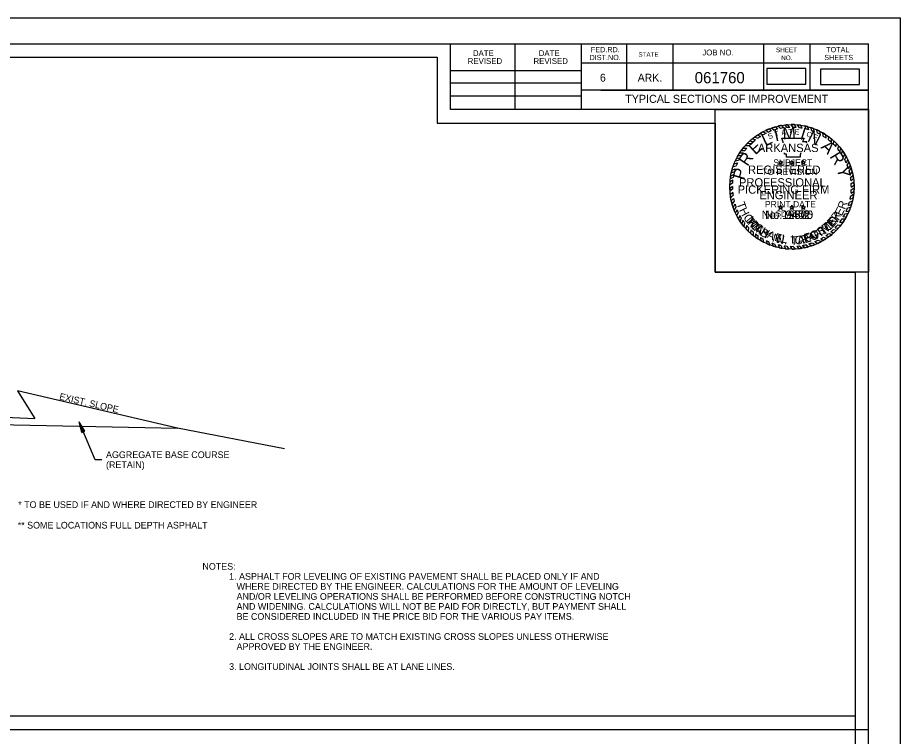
# Model space of a CAD drawing. Extents: x -124 to 3209, y -40 to 2094.
# Drawn here: x 1887 to 3209, y 1017 to 2094 of the extents above; entities that cross this region are included whole.
import ezdxf

# ---------------------------------------------------------------- set-up
doc = ezdxf.new("R2010")
doc.units = 0
for name, color, linetype in [('Default', 7, 'Continuous'), ('R_Border', 7, 'Continuous'), ('R_Border Notes', 7, 'Continuous'), ('R_Border Plan-Plan', 7, 'Continuous'), ('R_No Plot', 7, 'Continuous'), ('STAMP_PE_CRAFTON', 7, 'Continuous'), ('STAMP_PE_FOSTER', 7, 'Continuous'), ('STAMP_PE_SEAL-INFO', 7, 'Continuous'), ('STAMP_PE_TAEGTMEYER', 7, 'Continuous'), ('STAMP_PE_TXT', 7, 'Continuous'), ('STAMP_PRELIMINARY', 7, 'Continuous'), ('Text', 7, 'Continuous')]:
    doc.layers.add(name, color=color, linetype=linetype)

msp = doc.modelspace()

# ---------------------------------------------------------------- linework, layer by layer
at = {"layer": 'Default'}
for p, q in [((1886.3, 1534.5), (1912.2, 1493.4)), ((2126.3, 1478.9), (1886.3, 1534.5)), ((1685.5, 1502.5), (1912.2, 1493.4)), ((1706.3, 1487.1), (2126.3, 1478.9)), ((2286.3, 1447.9), (2126.3, 1478.9))]:
    msp.add_line(p, q, dxfattribs=at)
for points in [[(3009.4, 1994.1), (3067.8, 1994.1), (3067.8, 2017.2), (3009.4, 2017.2)], [(3089.7, 1993.3), (3148, 1993.3), (3148, 2016.4), (3089.7, 2016.4)]]:
    msp.add_lwpolyline(points, close=True, dxfattribs=at)
at = {"layer": 'R_Border'}
for p, q in [((0, 2054.6), (3161.8, 2054.6)), ((2535.4, 1955.8), (2535.4, 2054.6)), ((2632.2, 1955.8), (2632.2, 2054.6)), ((2730.8, 2054.6), (2730.8, 1955.8)), ((2799.2, 2054.6), (2799.2, 1985.2)), ((2868.6, 2054.6), (2868.6, 1985.2)), ((3004.4, 2054.6), (3004.4, 1985.2)), ((3073.8, 2054.6), (3073.8, 1985.2)), ((3161.8, 0), (3161.8, 2054.6)), ((3161.8, 2025.2), (2730.8, 2025.2)), ((3161.8, 2025.4), (3161.8, 2025.4)), ((2535.4, 2014.4), (2730.8, 2014.4)), ((2535.4, 1995.8), (2730.8, 1995.8)), ((3161.8, 1985.2), (2730.8, 1985.2)), ((2760.4, 1985.2), (3161.8, 1985.2)), ((2535.4, 1976.4), (2730.8, 1976.4)), ((3161.8, 1955.8), (2535.4, 1955.8))]:
    msp.add_line(p, q, dxfattribs=at)
at = {"layer": 'R_Border Plan-Plan'}
msp.add_line((0, 1027.3), (3161.8, 1027.3), dxfattribs=at)
at = {"layer": 'R_No Plot'}
for points in [[(-124.1, 2093.5), (3209.3, 2093.5), (3209.3, -39.8), (-124.1, -39.8)], [(3141.8, 1047.3), (20, 1047.3), (20, 2034.6), (2515.4, 2034.6), (2515.4, 1935.8), (2690.8, 1935.8), (2931.8, 1935.8), (2931.8, 1712.5), (3141.8, 1712.5)], [(20, 2034.6), (2515.4, 2034.6), (2515.4, 1935.8), (2690.8, 1935.8), (2931.8, 1935.8), (2931.8, 1712.5), (3141.8, 1712.5), (3141.8, 20), (20, 20)], [(2931.8, 1955.8), (3161.8, 1955.8), (3161.8, 1712.5), (2931.8, 1712.5)]]:
    msp.add_lwpolyline(points, close=True, dxfattribs=at)
at = {"layer": 'STAMP_PE_SEAL-INFO'}
for p, q in [((3031, 1932.1), (3034, 1928.4)), ((3036.2, 1932.8), (3039, 1929)), ((3043.5, 1929.3), (3040.4, 1933.2)), ((3048.5, 1929.3), (3045.7, 1933.4)), ((3053.1, 1929.1), (3050.5, 1933.4)), ((3058.1, 1928.6), (3055.2, 1933.1)), ((3062.4, 1928), (3059.8, 1932.5)), ((3068, 1926.8), (3066.3, 1931.4)), ((2999, 1920.3), (3003.4, 1918.1)), ((3003.5, 1922.8), (3008.2, 1920.6)), ((3007.8, 1924.9), (3011.7, 1922.2)), ((3012.9, 1927.1), (3015.9, 1923.8)), ((3016.4, 1928.4), (3020.2, 1925.3)), ((3022.3, 1930.2), (3025.2, 1926.7)), ((3026.2, 1931.1), (3029.7, 1927.7)), ((3072, 1925.7), (3070.4, 1930.4)), ((3076.5, 1924.2), (3075.1, 1929)), ((3080.7, 1922.6), (3079.3, 1927.6)), ((3085.3, 1920.6), (3084.3, 1925.6)), ((3089.8, 1918.3), (3088.9, 1923.4)), ((3093.7, 1916), (3093.3, 1921)), ((3098, 1913.2), (3097.7, 1918.3)), ((2980.4, 1905.7), (2985.9, 1905.3)), ((2983.8, 1908.9), (2988.4, 1907.5)), ((2987.2, 1911.9), (2992.5, 1910.9)), ((2991, 1915.2), (2995.5, 1913.1)), ((2995.2, 1917.9), (2999.6, 1915.8)), ((3031.5, 1913.1), (3065, 1913.1)), ((3032.7, 1910.1), (3031.5, 1913.1)), ((3033.8, 1907.1), (3032.7, 1910.1)), ((3033.9, 1905.9), (3033.8, 1907.1)), ((3065, 1913.1), (3062.7, 1908.2)), ((3062.7, 1908.2), (3069, 1908.2)), ((3069, 1908.2), (3067.6, 1905.9)), ((3101.6, 1910.5), (3102, 1915.4)), ((3106.1, 1906.8), (3106.3, 1912)), ((3109.2, 1903.9), (3109.9, 1908.8)), ((3112.8, 1900.1), (3113.5, 1905.4)), ((2971, 1894.4), (2976, 1894.4)), ((2973.7, 1898.1), (2979.2, 1898.3)), ((2977.2, 1902.2), (2982.4, 1901.9)), ((3115.5, 1897), (3116.9, 1901.7)), ((3118.8, 1892.8), (3120.1, 1897.8)), ((3121, 1889.6), (3122.8, 1894.3)), ((2962, 1878.9), (2967, 1879.9)), ((2963.8, 1882.7), (2968.8, 1883.4)), ((2966.1, 1887), (2971, 1887.2)), ((2968.6, 1891), (2973.8, 1891.3)), ((3035.8, 1888.9), (3035.5, 1891)), ((3038.9, 1888.9), (3035.8, 1888.9)), ((3038.9, 1884.6), (3038.9, 1888.9)), ((3059.2, 1884.6), (3038.9, 1884.6)), ((3059.4, 1887.9), (3059.2, 1884.6)), ((3060.1, 1891), (3059.4, 1887.9)), ((3124.1, 1884.7), (3125.9, 1889.6)), ((3126.1, 1881), (3128.3, 1885.4)), ((3128.4, 1876.2), (3130.6, 1881)), ((2957, 1865.4), (2961.8, 1867.1)), ((2958.6, 1870.5), (2963.5, 1871.8)), ((2960.1, 1874.5), (2965.2, 1876)), ((3129.8, 1872.8), (3132.4, 1877.1)), ((3131.7, 1867.3), (3134.4, 1872)), ((3132.8, 1863.7), (3135.7, 1868.2)), ((2958.8, 1854.3), (2954.3, 1852.1)), ((2959.6, 1858.9), (2955, 1856.4)), ((2956, 1861.4), (2960.7, 1863.3)), ((3134.1, 1858.1), (3137.3, 1862.5)), ((3134.8, 1854.3), (3138.4, 1857.8)), ((3135.5, 1849.2), (3139.2, 1852.5)), ((2957.8, 1845.7), (2953.6, 1843.1)), ((2957.7, 1840.8), (2953.6, 1837.4)), ((2958.2, 1850), (2953.8, 1847.1)), ((3135.8, 1845), (3139.7, 1847.9)), ((3135.9, 1839.8), (3140, 1843)), ((2957.7, 1836.7), (2953.8, 1833.5)), ((2958.1, 1831.8), (2954.4, 1828.2)), ((2958.6, 1827.5), (2955, 1823.7)), ((3134.9, 1826.8), (3139.3, 1829)), ((3135.4, 1830.7), (3139.8, 1833.3)), ((3135.8, 1835.8), (3140, 1838.5)), ((2959.4, 1822.9), (2956, 1819.2)), ((2960.3, 1818.7), (2957.2, 1814.5)), ((2961.5, 1814.2), (2958.6, 1810)), ((3131.5, 1812.4), (3136.4, 1814.4)), ((3132.9, 1817.3), (3137.7, 1819.3)), ((3134, 1821.8), (3138.6, 1823.8)), ((2963, 1810), (2960.1, 1805.9)), ((2964.6, 1805.7), (2962, 1801.5)), ((2966.3, 1801.9), (2964.1, 1797.3)), ((3126.4, 1800), (3131.2, 1800.7)), ((3128, 1803.4), (3132.9, 1804.4)), ((3130.1, 1808.6), (3134.9, 1809.9)), ((2968.7, 1797.3), (2966.8, 1792.4)), ((2971, 1793.3), (2969.2, 1788.6)), ((2973.1, 1790.1), (2972, 1784.6)), ((2975.9, 1786.2), (2974.9, 1780.9)), ((3118.5, 1787.3), (3123.6, 1787.3)), ((3121.9, 1792.3), (3126.7, 1792.2)), ((3123.6, 1795.1), (3128.7, 1795.6)), ((2978.9, 1782.5), (2978, 1777.3)), ((2981.9, 1779.1), (2981.3, 1773.9)), ((2985.2, 1775.8), (2984.9, 1770.5)), ((2988.6, 1772.7), (2988.6, 1767.4)), ((3105, 1772.7), (3109.7, 1771.4)), ((3109.1, 1776.4), (3113.5, 1775.1)), ((3111.6, 1779), (3116.4, 1778.2)), ((3115.5, 1783.4), (3120.1, 1782.6)), ((2992.2, 1769.8), (2992.4, 1764.5)), ((2995.6, 1767.3), (2996, 1762.1)), ((2999.9, 1764.5), (3000.5, 1759.3)), ((3003.4, 1762.4), (3004.3, 1757.3)), ((3008.2, 1759.9), (3009.7, 1754.7)), ((3086, 1760.2), (3090.9, 1758.1)), ((3090.1, 1762.3), (3094.3, 1760)), ((3094.3, 1764.8), (3098.8, 1762.8)), ((3097.7, 1767.1), (3102.1, 1765.2)), ((3102.3, 1770.5), (3107, 1769)), ((3011.9, 1758.2), (3013.6, 1753.1)), ((3016.8, 1756.3), (3018.9, 1751.3)), ((3020.9, 1754.9), (3023.2, 1750)), ((3026, 1753.6), (3028.1, 1748.9)), ((3030, 1752.7), (3032.4, 1748.1)), ((3035, 1751.9), (3037.4, 1747.5)), ((3039.3, 1751.4), (3042.1, 1747.1)), ((3044.2, 1751.1), (3047.2, 1747)), ((3048.8, 1751.1), (3052.2, 1747.2)), ((3054, 1751.4), (3057.2, 1747.6)), ((3058.4, 1751.8), (3062.1, 1748.3)), ((3062.8, 1752.5), (3066.7, 1749.1)), ((3067.7, 1753.6), (3071.5, 1750.3)), ((3072.3, 1754.8), (3076.5, 1751.9)), ((3077.3, 1756.5), (3081.7, 1753.8)), ((3081.4, 1758.1), (3085.7, 1755.5))]:
    msp.add_line(p, q, dxfattribs=at)
for radius, start, end in [(93.2, 99.7525, 102.7765), (93.2, 93.9381, 96.5517), (93.2, 87.7298, 90.6707), (93.2, 81.9732, 84.8236), (93.2, 75.3125, 77.9426), (93.2, 117.6544, 120.8099), (89.1, 115.6869, 119.1583), (93.2, 111.3124, 114.7026), (89.1, 110.3086, 113.1659), (93.2, 105.2339, 109.0352), (89.1, 104.0352, 107.3615), (89.1, 98.258, 101.0329), (89.1, 92.1102, 95.0367), (89.1, 85.9628, 88.9097), (89.1, 79.9264, 82.696), (89.1, 73.5575, 76.2314), (93.2, 69.6061, 72.3058), (89.1, 67.6248, 70.504), (93.2, 63.1329, 66.2704), (89.1, 61.1558, 64.3784), (93.2, 56.9003, 60.0942), (93.2, 135.4021, 138.3031), (89.1, 133.1331, 136.2562), (93.2, 129.7326, 132.5376), (89.1, 127.5297, 130.9683), (93.2, 123.6199, 126.5906), (89.1, 121.9746, 125.11), (89.1, 54.9238, 58.2702), (89.1, 48.3016, 52.0395), (93.2, 50.3492, 53.7159), (93.2, 44.3405, 47.3929), (93.2, 141.6056, 144.4486), (89.1, 139.301, 142.5873), (89.1, 42.2212, 45.5512), (89.1, 36.135, 39.5311), (93.2, 38.1247, 41.2316), (93.2, 31.9614, 35.4294), (93.2, 152.864, 155.5189), (93.2, 147.0072, 149.899), (89.1, 151.0315, 153.573), (89.1, 145.0197, 148.2104), (89.1, 29.9032, 33.6645), (89.1, 23.7732, 27.2211), (93.2, 25.9391, 29.0125), (93.2, 164.3068, 166.894), (93.2, 158.4077, 161.0701), (89.1, 162.4331, 165.0013), (89.1, 156.3402, 159.2319), (89.1, 17.6802, 21.4251), (93.2, 19.9538, 23.3141), (93.2, 13.8421, 17.4447), (93.2, 170.0003, 172.6878), (89.1, 167.9048, 170.9039), (89.1, 11.5444, 15.2364), (89.1, 5.7599, 9.0606), (93.2, 7.5852, 10.8621), (93.2, 175.7409, 178.2066), (89.1, 179.6454, 182.2633), (89.1, 173.73, 176.4734), (89.1, 359.7329, 3.0639), (93.2, 1.7215, 4.7268), (93.2, 181.7251, 184.1626), (93.2, 187.4204, 190.1927), (89.1, 185.4539, 188.234), (89.1, 348.0778, 351.3435), (89.1, 353.8632, 357.1274), (93.2, 349.8305, 353.0885), (93.2, 355.7156, 358.9569), (93.2, 193.0369, 195.9973), (89.1, 191.2274, 193.9858), (89.1, 196.9675, 199.8353), (89.1, 341.777, 345.0925), (93.2, 343.8925, 347.035), (93.2, 198.8967, 201.6281), (93.2, 204.5479, 207.4328), (89.1, 202.7761, 205.4791), (89.1, 329.5549, 333.2076), (89.1, 335.6038, 339.1858), (93.2, 331.4037, 334.9332), (93.2, 337.3837, 340.9933), (93.2, 210.8636, 213.6571), (89.1, 208.7883, 211.7934), (89.1, 214.1838, 217.2747), (89.1, 323.5851, 327.4407), (93.2, 325.4405, 328.9872), (93.2, 216.6115, 219.491), (93.2, 222.48, 225.3801), (89.1, 220.3909, 223.3056), (89.1, 226.2494, 229.2407), (89.1, 310.7744, 314.3161), (93.2, 312.4518, 315.6633), (89.1, 316.6531, 320.3711), (93.2, 318.2846, 321.8043), (93.2, 228.3665, 231.348), (89.1, 232.229, 234.9336), (93.2, 234.295, 236.9452), (89.1, 238.2223, 240.8353), (93.2, 240.1977, 242.8613), (89.1, 244.3204, 246.9486), (89.1, 292.8745, 296.1185), (89.1, 299.0768, 302.1724), (93.2, 300.621, 303.8703), (89.1, 304.823, 308.5143), (93.2, 306.3721, 310.208), (93.2, 246.576, 249.1558), (89.1, 250.3491, 253.1216), (93.2, 252.5967, 255.3252), (89.1, 256.505, 259.1192), (93.2, 258.4433, 261.1398), (89.1, 262.3783, 265.2012), (93.2, 264.1978, 267.1009), (89.1, 268.3215, 271.277), (93.2, 270.2548, 273.3361), (89.1, 274.6157, 277.4486), (93.2, 276.4239, 279.4357), (89.1, 280.3459, 283.5814), (93.2, 282.3199, 285.3702), (89.1, 286.6423, 289.9783), (93.2, 288.5709, 291.9733), (93.2, 294.6481, 298.2166)]:
    msp.add_arc((3046.8, 1840.2), radius, start, end, dxfattribs=at)
at = {"layer": 'STAMP_PE_TXT'}
for p, q in [((3029.1, 1877.4), (3029.8, 1879.7)), ((3029.8, 1879.7), (3030.6, 1877.4)), ((3046, 1877.4), (3046.8, 1879.7)), ((3046.8, 1879.7), (3047.6, 1877.4)), ((3063, 1877.4), (3063.8, 1879.7)), ((3063.8, 1879.7), (3064.5, 1877.4)), ((3028.6, 1875.9), (3026.6, 1877.4)), ((3026.6, 1877.4), (3029.1, 1877.4)), ((3027.8, 1873.6), (3028.6, 1875.9)), ((3029.8, 1875), (3027.8, 1873.6)), ((3031.8, 1873.6), (3029.8, 1875)), ((3030.6, 1877.4), (3033, 1877.4)), ((3033, 1877.4), (3031, 1875.9)), ((3031, 1875.9), (3031.8, 1873.6)), ((3045.6, 1875.9), (3043.6, 1877.4)), ((3043.6, 1877.4), (3046, 1877.4)), ((3044.8, 1873.6), (3045.6, 1875.9)), ((3046.8, 1875), (3044.8, 1873.6)), ((3048.8, 1873.6), (3046.8, 1875)), ((3047.6, 1877.4), (3050, 1877.4)), ((3050, 1877.4), (3048, 1875.9)), ((3048, 1875.9), (3048.8, 1873.6)), ((3062.6, 1875.9), (3060.6, 1877.4)), ((3060.6, 1877.4), (3063, 1877.4)), ((3061.8, 1873.6), (3062.6, 1875.9)), ((3063.8, 1875), (3061.8, 1873.6)), ((3065.8, 1873.6), (3063.8, 1875)), ((3064.5, 1877.4), (3067, 1877.4)), ((3067, 1877.4), (3065, 1875.9)), ((3065, 1875.9), (3065.8, 1873.6)), ((3029.1, 1810.3), (3029.8, 1812.6)), ((3029.8, 1812.6), (3030.6, 1810.3)), ((3046, 1810.3), (3046.8, 1812.6)), ((3046.8, 1812.6), (3047.6, 1810.3)), ((3063, 1810.3), (3063.8, 1812.6)), ((3063.8, 1812.6), (3064.5, 1810.3)), ((3028.6, 1808.9), (3026.6, 1810.3)), ((3026.6, 1810.3), (3029.1, 1810.3)), ((3027.8, 1806.5), (3028.6, 1808.9)), ((3029.8, 1808), (3027.8, 1806.5)), ((3031.8, 1806.5), (3029.8, 1808)), ((3030.6, 1810.3), (3033, 1810.3)), ((3033, 1810.3), (3031, 1808.9)), ((3031, 1808.9), (3031.8, 1806.5)), ((3045.6, 1808.9), (3043.6, 1810.3)), ((3043.6, 1810.3), (3046, 1810.3)), ((3044.8, 1806.5), (3045.6, 1808.9)), ((3046.8, 1808), (3044.8, 1806.5)), ((3048.8, 1806.5), (3046.8, 1808)), ((3047.6, 1810.3), (3050, 1810.3)), ((3050, 1810.3), (3048, 1808.9)), ((3048, 1808.9), (3048.8, 1806.5)), ((3062.6, 1808.9), (3060.6, 1810.3)), ((3060.6, 1810.3), (3063, 1810.3)), ((3061.8, 1806.5), (3062.6, 1808.9)), ((3063.8, 1808), (3061.8, 1806.5)), ((3065.8, 1806.5), (3063.8, 1808)), ((3064.5, 1810.3), (3067, 1810.3)), ((3067, 1810.3), (3065, 1808.9)), ((3065, 1808.9), (3065.8, 1806.5))]:
    msp.add_line(p, q, dxfattribs=at)
at = {"layer": 'STAMP_PRELIMINARY'}
msp.add_circle((3046.8, 1840.2), 93.2, dxfattribs=at)
at = {"layer": 'Text'}
for p, q in [((1886.3, 1534.5), (1892.8, 1524.2)), ((1982.9, 1472.4), (1978.8, 1488.1)), ((1987.3, 1474.3), (1978.8, 1488.1)), ((1983.2, 1472.6), (1979.8, 1485.6)), ((1986.9, 1474.1), (1979.8, 1485.6)), ((1986.5, 1474), (1980.9, 1483.1)), ((1983.6, 1472.7), (1980.9, 1483.1)), ((1984, 1472.9), (1982, 1480.6)), ((1986.2, 1473.8), (1982, 1480.6)), ((1982.9, 1472.4), (1987.3, 1474.3)), ((1985.8, 1473.7), (1983, 1478.1)), ((1984.4, 1473), (1983, 1478.1)), ((1985.4, 1473.5), (1984.1, 1475.7)), ((1984.7, 1473.2), (1984.1, 1475.7))]:
    msp.add_line(p, q, dxfattribs=at)
msp.add_lwpolyline([(2012.9, 1431.6), (2002.9, 1431.6), (1978.8, 1488.1)], dxfattribs=at)

# ---------------------------------------------------------------- texts
at = {"layer": 'R_Border'}
for s, height, p in [('DATE', 8.79, (2568.8, 2036)), ('DATE', 8.79, (2667.4, 2036)), ('DIST.NO.', 7.82, (2743.6, 2030)), ('FED.RD.', 7.82, (2745.6, 2041.8)), ('STATE', 6.84, (2816.8, 2035)), ('JOB NO.', 8.79, (2912.6, 2037)), ('SHEET', 6.84, (3023, 2041.8)), ('SHEETS', 7.82, (3095.4, 2030)), ('TOTAL', 7.82, (3098.2, 2041.8)), ('REVISED', 8.79, (2561, 2024.2)), ('REVISED', 8.79, (2659.6, 2024.2)), ('NO.', 6.84, (3030.8, 2030)), ('6', 11.7, (2759.2, 1997.8)), ('ARK.', 11.72, (2815.8, 1997.8))]:
    msp.add_text(s, height=height, dxfattribs=at).set_placement(p)
at = {"layer": 'R_Border Notes'}
for s, height, p in [('061760', 16.8, (2901.2, 1995.3)), ('TYPICAL SECTIONS OF IMPROVEMENT', 12, (2797.1, 1966))]:
    msp.add_text(s, height=height, dxfattribs=at).set_placement(p)
at = {"layer": 'STAMP_PE_CRAFTON'}
msp.add_text('No. 12370', height=12.5, dxfattribs=at).set_placement((3001.4, 1792.2))
for s, rotation, p in [('T', 310.7442, (2976.5, 1789.2)), ('O', 317.6422, (2983.1, 1781.1)), ('O', 41.8391, (3101.2, 1772.6)), ('N', 49.2411, (3109.6, 1780.4)), ('N', 324.4537, (2991.6, 1773.2)), ('Y', 331.1686, (3001.9, 1766.1)), ('F', 28.7821, (3083.4, 1761.5)), ('T', 34.1136, (3092.6, 1766.6)), ('N', 347.4752, (3022.5, 1756.9)), ('C', 6.0117, (3051.5, 1753.6)), ('R', 14.8189, (3062.5, 1754.8)), ('A', 20.5125, (3073.6, 1757.8)), ('.', 356.8926, (3034.8, 1754.1))]:
    msp.add_text(s, height=12.5, rotation=rotation, dxfattribs=at).set_placement(p)
at = {"layer": 'STAMP_PE_FOSTER'}
msp.add_text('No. 9402', height=12.5, dxfattribs=at).set_placement((3006.7, 1792.2))
for s, rotation, p in [('R', 54.5031, (3114, 1788.3)), ('M', 308.339, (2978, 1790.4)), ('I', 314.1842, (2985.9, 1781.1)), ('T', 39.4194, (3098.2, 1772.6)), ('E', 46.9613, (3106.8, 1780.1)), ('C', 319.8733, (2989.5, 1777.5)), ('H', 327.7235, (2998.8, 1770.2)), ('A', 335.7276, (3008.6, 1764.4)), ('O', 23.719, (3077.6, 1761)), ('S', 31.7234, (3088.7, 1766.3)), ('E', 343.5779, (3020, 1759.7)), ('L', 350.8115, (3030.5, 1756.9)), ('L', 1.2666, (3045.9, 1755.3)), ('F', 15.8691, (3067.1, 1757.8)), ('.', 6.8035, (3056.4, 1755.9))]:
    msp.add_text(s, height=12, rotation=rotation, dxfattribs=at).set_placement(p)
at = {"layer": 'STAMP_PE_TAEGTMEYER'}
for s, rotation, p in [('T', 289.646, (2963.7, 1815.3)), ('R', 69.57, (3126.3, 1805.4)), ('H', 296.7339, (2967.3, 1805.5)), ('O', 303.7708, (2973.3, 1794.4)), ('Y', 53.9986, (3114.6, 1786.1)), ('E', 63.0984, (3121.3, 1795.6)), ('M', 314.2033, (2979.8, 1784.9)), ('M', 39.3, (3096.8, 1769.2)), ('E', 46.8094, (3107.2, 1778)), ('A', 321.0594, (2989.4, 1775.2)), ('S', 327.8239, (2997.7, 1768.8)), ('G', 23.3052, (3076.8, 1758.8)), ('T', 31.466, (3087.8, 1763.8)), ('N', 344.2727, (3016.7, 1758.7)), ('T', 3.0061, (3045.4, 1753.4)), ('A', 8.9826, (3055.9, 1754)), ('E', 17.6836, (3066.3, 1755.5)), ('.', 350.6464, (3028.8, 1755.4))]:
    msp.add_text(s, height=12.5, rotation=rotation, dxfattribs=at).set_placement(p)
msp.add_text('No. 19605', height=12.5, dxfattribs=at).set_placement((3001.4, 1792.2))
at = {"layer": 'STAMP_PE_TXT'}
for s, rotation, p in [('S', 23.5541, (3012.8, 1911.3)), ('T', 16.311, (3022, 1915)), ('A', 9.0679, (3031.6, 1917.5)), ('T', 1.8248, (3041.5, 1918.8)), ('E', 355.2002, (3050.6, 1918.9)), ('O', 342.2506, (3067.9, 1916.1)), ('F', 335.0075, (3077.5, 1912.7))]:
    msp.add_text(s, height=7.81, rotation=rotation, dxfattribs=at).set_placement(p)
for s, p in [('ARKANSAS', (2995.7, 1892.3)), ('REGISTERED', (2981, 1859.6)), ('PROFESSIONAL', (2967.5, 1840.6)), ('ENGINEER', (2997.9, 1821.6))]:
    msp.add_text(s, height=12.5, dxfattribs=at).set_placement(p)
at = {"layer": 'STAMP_PRELIMINARY'}
for s, rotation, p in [('L', 25.513, (3006.9, 1900.5)), ('I', 12.5248, (3022.2, 1908.1)), ('M', 3.1074, (3033.2, 1911.2)), ('I', 342.3164, (3057.8, 1911.9)), ('N', 333.9382, (3068.9, 1909.1)), ('E', 42.3578, (2992.1, 1887.2)), ('A', 315.6579, (3089.2, 1898.9)), ('R', 301.3831, (3102.9, 1885.7)), ('R', 56.2292, (2980.5, 1869.9)), ('P', 73.913, (2975, 1849.6)), ('Y', 283.2593, (3113.8, 1867.9))]:
    msp.add_text(s, height=18, rotation=rotation, dxfattribs=at).set_placement(p)
for s, height, p in [('SUBJECT', 9.6, (3018.8, 1871.7)), ('TO REVISION', 9.6, (3002.2, 1857.9)), ('PICKERING FIRM', 12.5, (2965.5, 1829.9)), ('PRINT DATE', 9.6, (3006.4, 1809.4)), ('$DATE$', 9.6, (3023.1, 1795.5))]:
    msp.add_text(s, height=height, dxfattribs=at).set_placement(p)
at = {"layer": 'Text'}
msp.add_text('EXIST. SLOPE', height=10, rotation=347.0379, dxfattribs=at).set_placement((1948.4, 1521.8))
for s, p in [('AGGREGATE BASE COURSE', (2019, 1434)), ('(RETAIN)', (2019, 1419)), ('* TO BE USED IF AND WHERE DIRECTED BY ENGINEER', (1887.5, 1359.3)), ('** SOME LOCATIONS FULL DEPTH ASPHALT', (1886.7, 1328.5)), ('NOTES:', (2163.5, 1266.8)), ('1. ASPHALT FOR LEVELING OF EXISTING PAVEMENT SHALL BE PLACED ONLY IF AND', (2203.5, 1251.8)), ('   WHERE DIRECTED BY THE ENGINEER. CALCULATIONS FOR THE AMOUNT OF LEVELING', (2203.5, 1236.8)), ('   AND/OR LEVELING OPERATIONS SHALL BE PERFORMED BEFORE CONSTRUCTING NOTCH', (2203.5, 1221.8)), ('   AND WIDENING. CALCULATIONS WILL NOT BE PAID FOR DIRECTLY, BUT PAYMENT SHALL', (2203.5, 1206.8)), ('   BE CONSIDERED INCLUDED IN THE PRICE BID FOR THE VARIOUS PAY ITEMS. ', (2203.5, 1191.8)), ('2. ALL CROSS SLOPES ARE TO MATCH EXISTING CROSS SLOPES UNLESS OTHERWISE ', (2203.5, 1161.8)), ('   APPROVED BY THE ENGINEER. ', (2203.5, 1146.8)), ('3. LONGITUDINAL JOINTS SHALL BE AT LANE LINES.', (2203.5, 1116.8))]:
    msp.add_text(s, height=10, dxfattribs=at).set_placement(p)

doc.saveas('drawing.dxf')
